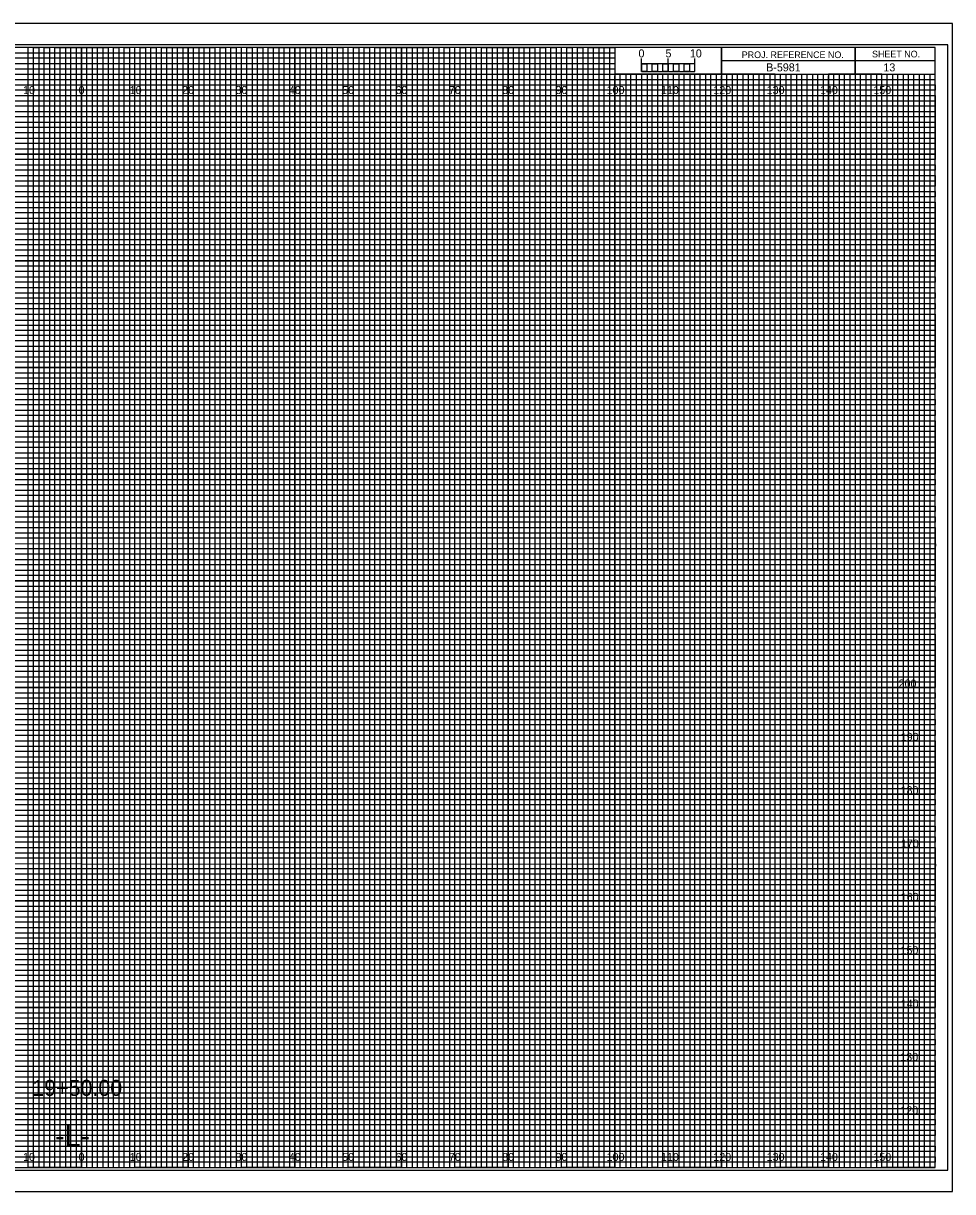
# Model space of a CAD drawing. Extents: x -13 to 323, y -5 to 4174.
# Drawn here: x 149.1 to 323.3, y 1535.5 to 1754.5 of the extents above; entities that cross this region are included whole.
import ezdxf

# ---------------------------------------------------------------- set-up
doc = ezdxf.new("R2010")
doc.units = 0
for name, color, linetype in [('Exist Cross Section Cell', 7, 'Continuous'), ('Exist XS Center Line Elevation Label', 7, 'Continuous'), ('Exist XS Ground Line', 7, 'Continuous'), ('Prop CMT Concrete Structures', 7, 'Continuous'), ('Prop CMT Guardrail Graphics', 7, 'Continuous'), ('Prop CMT Pvmt Course 1', 7, 'Continuous'), ('Prop CMT Pvmt Course 2', 7, 'Continuous'), ('Prop CMT Pvmt Course 3', 7, 'Continuous'), ('Prop CMT Pvmt Surface', 7, 'Continuous'), ('Prop CMT Shld Paved Course 1', 7, 'Continuous'), ('Prop CMT Shld Paved Course 2', 7, 'Continuous'), ('Prop CMT Shld Paved Course 3', 7, 'Continuous'), ('Prop CMT Subgrade Earthwork', 7, 'Continuous'), ('Prop XS Ditch Standard Text', 7, 'Continuous'), ('Prop XS SE Text', 7, 'Continuous'), ('Prop XS Side Slope Text', 7, 'Continuous'), ('Scratch_Level_0', 7, 'Continuous')]:
    doc.layers.add(name, color=color, linetype=linetype)

msp = doc.modelspace()

# ---------------------------------------------------------------- linework, layer by layer
at = {"layer": 'Exist XS Center Line Elevation Label'}
for points in [[(145, 1540), (155, 1540), (155, 1750), (165, 1750), (165, 1540), (175, 1540), (175, 1750), (185, 1750), (185, 1540), (195, 1540), (195, 1750), (205, 1750), (205, 1540), (215, 1540), (215, 1750), (225, 1750), (225, 1540), (235, 1540), (235, 1750), (245, 1750), (245, 1540), (255, 1540), (255, 1750), (259.93, 1750), (260, 1750), (260, 1745), (264.99, 1745), (264.99, 1540), (275, 1540), (275, 1745), (285, 1745), (285, 1540), (295, 1540), (295, 1745), (305, 1745), (305, 1540), (315, 1540), (315, 1745)], [(0, 1745), (275, 1745)], [(0, 1725), (320, 1725), (320, 1735), (0, 1735)], [(0, 1705), (320, 1705), (320, 1715), (0, 1715)], [(0, 1685), (320, 1685), (320, 1695), (0, 1695)], [(0, 1665), (320, 1665), (320, 1675), (0, 1675)], [(0, 1645), (320, 1645), (320, 1655), (0, 1655)], [(0, 1625), (320, 1625), (320, 1635), (0, 1635)], [(0, 1605), (320, 1605), (320, 1615), (0, 1615)], [(0, 1585), (320, 1585), (320, 1595), (0, 1595)], [(0, 1565), (320, 1565), (320, 1575), (0, 1575)], [(0, 1545), (320, 1545), (320, 1555), (0, 1555)]]:
    msp.add_lwpolyline(points, dxfattribs=at)
at = {"layer": 'Exist XS Ground Line'}
for p, q in [((150, 1750), (140, 1750)), ((150, 1540), (150, 1750)), ((170, 1750), (160, 1750)), ((160, 1750), (160, 1540)), ((170, 1540), (170, 1750)), ((190, 1750), (180, 1750)), ((180, 1750), (180, 1540)), ((190, 1540), (190, 1750)), ((210, 1750), (200, 1750)), ((200, 1750), (200, 1540)), ((210, 1540), (210, 1750)), ((230, 1750), (220, 1750)), ((220, 1750), (220, 1540)), ((230, 1540), (230, 1750)), ((250, 1750), (240, 1750)), ((240, 1750), (240, 1540)), ((250, 1540), (250, 1750)), ((260, 1750), (260, 1540)), ((270, 1540), (270, 1745)), ((290, 1745), (280, 1745)), ((280, 1745), (280, 1540)), ((290, 1540), (290, 1745)), ((310, 1745), (300, 1745)), ((300, 1745), (300, 1540)), ((310, 1540), (310, 1745)), ((160, 1540), (150, 1540)), ((180, 1540), (170, 1540)), ((200, 1540), (190, 1540)), ((220, 1540), (210, 1540)), ((240, 1540), (230, 1540)), ((260, 1540), (250, 1540)), ((280, 1540), (270, 1540)), ((300, 1540), (290, 1540)), ((320, 1540), (310, 1540)), ((320, 1540), (320, 1540))]:
    msp.add_line(p, q, dxfattribs=at)
for points in [[(0, 1740), (320, 1740), (320, 1730), (0, 1730)], [(0, 1720), (320, 1720), (320, 1710), (0, 1710)], [(0, 1700), (320, 1700), (320, 1690), (0, 1690)], [(0, 1680), (320, 1680), (320, 1670), (0, 1670)], [(0, 1660), (320, 1660), (320, 1650), (0, 1650)], [(0, 1640), (320, 1640), (320, 1630), (0, 1630)], [(0, 1620), (320, 1620), (320, 1610), (0, 1610)], [(0, 1600), (320, 1600), (320, 1590), (0, 1590)], [(0, 1580), (320, 1580), (320, 1570), (0, 1570)], [(0, 1560), (320, 1560), (320, 1550), (0, 1550)]]:
    msp.add_lwpolyline(points, dxfattribs=at)
at = {"layer": 'Prop CMT Pvmt Course 1'}
for p, q in [((323.3, 1754.5), (-13.4, 1754.5)), ((-13.4, 1535.5), (323.3, 1535.5))]:
    msp.add_line(p, q, dxfattribs=at)
at = {"layer": 'Prop CMT Pvmt Course 2'}
msp.add_lwpolyline([(-13.4, 1535.5), (323.3, 1535.5), (323.3, 1754.5), (-13.4, 1754.5)], close=True, dxfattribs=at)
at = {"layer": 'Prop CMT Pvmt Course 3'}
msp.add_lwpolyline([(-10.8, 1539.5), (322.4, 1539.5), (322.4, 1750.5), (-10.8, 1750.5)], close=True, dxfattribs=at)
at = {"layer": 'Prop CMT Shld Paved Course 1'}
for p, q in [((305, 1750), (305, 1745)), ((305, 1745), (305, 1750)), ((280, 1747.5), (280, 1745)), ((320, 1747.49), (280, 1747.49)), ((280, 1745), (320, 1745))]:
    msp.add_line(p, q, dxfattribs=at)
for points in [[(320, 1750), (0, 1750), (0, 1540), (320, 1540)], [(280, 1750), (260, 1750), (260, 1745.03), (280, 1745.03)], [(320, 1750), (280, 1750), (280, 1745), (320, 1745)]]:
    msp.add_lwpolyline(points, close=True, dxfattribs=at)
at = {"layer": 'Prop CMT Shld Paved Course 2'}
for p, q in [((267, 1745), (266.01, 1745)), ((266.01, 1745), (266.01, 1540)), ((267, 1540), (267, 1745)), ((269, 1745), (268, 1745)), ((268, 1745), (268, 1540)), ((269, 1540), (269, 1745)), ((266.01, 1540), (265, 1540)), ((268, 1540), (267, 1540))]:
    msp.add_line(p, q, dxfattribs=at)
for points in [[(150, 1540), (151, 1540), (151, 1750), (152, 1750), (152, 1540)], [(152, 1540), (153, 1540), (153, 1750), (154, 1750), (154, 1540)], [(155, 1540), (156, 1540), (156, 1750), (157, 1750), (157, 1540)], [(157, 1540), (158, 1540), (158, 1750), (159, 1750), (159, 1540)], [(160, 1540), (161, 1540), (161, 1750), (162, 1750), (162, 1540)], [(162, 1540), (163, 1540), (163, 1750), (164, 1750), (164, 1540)], [(165, 1540), (166, 1540), (166, 1750), (167, 1750), (167, 1540)], [(167, 1540), (168, 1540), (168, 1750), (169, 1750), (169, 1540)], [(170, 1540), (171, 1540), (171, 1750), (172, 1750), (172, 1540)], [(172, 1540), (173, 1540), (173, 1750), (174, 1750), (174, 1540)], [(175, 1540), (176, 1540), (176, 1750), (177, 1750), (177, 1540)], [(177, 1540), (178, 1540), (178, 1750), (179, 1750), (179, 1540)], [(180, 1540), (181, 1540), (181, 1750), (182, 1750), (182, 1540)], [(182, 1540), (183, 1540), (183, 1750), (184, 1750), (184, 1540)], [(185, 1540), (186, 1540), (186, 1750), (187, 1750), (187, 1540)], [(187, 1540), (188, 1540), (188, 1750), (189, 1750), (189, 1540)], [(190, 1540), (191, 1540), (191, 1750), (192, 1750), (192, 1540)], [(192, 1540), (193, 1540), (193, 1750), (194, 1750), (194, 1540)], [(195, 1540), (196, 1540), (196, 1750), (197, 1750), (197, 1540)], [(197, 1540), (198, 1540), (198, 1750), (199, 1750), (199, 1540)], [(200, 1540), (201, 1540), (201, 1750), (202, 1750), (202, 1540)], [(202, 1540), (203, 1540), (203, 1750), (204, 1750), (204, 1540)], [(205, 1540), (206, 1540), (206, 1750), (207, 1750), (207, 1540)], [(207, 1540), (208, 1540), (208, 1750), (209, 1750), (209, 1540)], [(210, 1540), (211, 1540), (211, 1750), (212, 1750), (212, 1540)], [(212, 1540), (213, 1540), (213, 1750), (214, 1750), (214, 1540)], [(215, 1540), (216, 1540), (216, 1750), (217, 1750), (217, 1540)], [(217, 1540), (218, 1540), (218, 1750), (219, 1750), (219, 1540)], [(220, 1540), (221, 1540), (221, 1750), (222, 1750), (222, 1540)], [(222, 1540), (223, 1540), (223, 1750), (224, 1750), (224, 1540)], [(225, 1540), (226, 1540), (226, 1750), (227, 1750), (227, 1540)], [(227, 1540), (228, 1540), (228, 1750), (229, 1750), (229, 1540)], [(230, 1540), (231, 1540), (231, 1750), (232, 1750), (232, 1540)], [(232, 1540), (233, 1540), (233, 1750), (234, 1750), (234, 1540)], [(235, 1540), (236, 1540), (236, 1750), (237, 1750), (237, 1540)], [(237, 1540), (238, 1540), (238, 1750), (239, 1750), (239, 1540)], [(240, 1540), (241, 1540), (241, 1750), (242, 1750), (242, 1540)], [(242, 1540), (243, 1540), (243, 1750), (244, 1750), (244, 1540)], [(245, 1540), (246, 1540), (246, 1750), (247, 1750), (247, 1540)], [(247, 1540), (248, 1540), (248, 1750), (249, 1750), (249, 1540)], [(250, 1540), (251, 1540), (251, 1750), (252, 1750), (252, 1540)], [(252, 1540), (253, 1540), (253, 1750), (254, 1750), (254, 1540)], [(255, 1540), (256, 1540), (256, 1750), (257, 1750), (257, 1540)], [(257, 1540), (258, 1540), (258, 1750), (259, 1750), (259, 1540)], [(260, 1540), (261, 1540), (261, 1745), (262.02, 1745), (262.02, 1540)], [(262, 1540), (263, 1540), (263, 1745), (263.99, 1745), (263.99, 1540)], [(270, 1540), (270.98, 1540), (270.98, 1745), (272, 1745), (272, 1540)], [(272, 1540), (273, 1540), (273, 1745), (274.05, 1745), (274.05, 1540)], [(275, 1540), (276, 1540), (276, 1745), (277, 1745), (277, 1540)], [(277, 1540), (278, 1540), (278, 1745), (279, 1745), (279, 1540)], [(280, 1540), (281, 1540), (281, 1745), (282, 1745), (282, 1540)], [(282, 1540), (283, 1540), (283, 1745), (284, 1745), (284, 1540)], [(285, 1540), (286, 1540), (286, 1745), (287, 1745), (287, 1540)], [(287, 1540), (288, 1540), (288, 1745), (289, 1745), (289, 1540)], [(290, 1540), (291, 1540), (291, 1745), (292, 1745), (292, 1540)], [(292, 1540), (293, 1540), (293, 1745), (294, 1745), (294, 1540)], [(295, 1540), (296, 1540), (296, 1745), (297, 1745), (297, 1540)], [(297, 1540), (298, 1540), (298, 1745), (299, 1745), (299, 1540)], [(300, 1540), (301, 1540), (301, 1745), (302, 1745), (302, 1540)], [(302, 1540), (303, 1540), (303, 1745), (304, 1745), (304, 1540)], [(305, 1540), (306, 1540), (306, 1745), (307, 1745), (307, 1540)], [(307, 1540), (308, 1540), (308, 1745), (309, 1745), (309, 1540)], [(310, 1540), (311, 1540), (311, 1745), (312, 1745), (312, 1540)], [(312, 1540), (313, 1540), (313, 1745), (314, 1745), (314, 1540)], [(315, 1540), (316, 1540), (316, 1745), (317, 1745), (317, 1540)], [(317, 1540), (318, 1540), (318, 1745), (319, 1745), (319, 1540)]]:
    msp.add_lwpolyline(points, dxfattribs=at)
at = {"layer": 'Prop CMT Shld Paved Course 3'}
for p, q in [((265, 1745.49), (265, 1747.9)), ((265, 1746.9), (265, 1747.9)), ((270, 1745.49), (270, 1747.9)), ((275, 1745.49), (275, 1747.9)), ((275, 1746.9), (275, 1747.9))]:
    msp.add_line(p, q, dxfattribs=at)
for points in [[(275, 1746.9), (265, 1746.9), (265, 1745.49), (275, 1745.49)], [(265, 1746.9), (266, 1746.9), (266, 1745.49), (265, 1745.49)], [(267, 1746.9), (268, 1746.9), (268, 1745.49), (267, 1745.49)], [(269, 1746.9), (270, 1746.9), (270, 1745.49), (269, 1745.49)], [(271, 1746.9), (272, 1746.9), (272, 1745.49), (271, 1745.49)], [(273, 1746.9), (274, 1746.9), (274, 1745.49), (273, 1745.49)]]:
    msp.add_lwpolyline(points, close=True, dxfattribs=at)
at = {"layer": 'Prop CMT Subgrade Earthwork'}
for p, q in [((150, 1540), (150, 1750)), ((160, 1540), (160, 1750)), ((170, 1540), (170, 1750)), ((180, 1540), (180, 1750)), ((190, 1540), (190, 1750)), ((200, 1540), (200, 1750)), ((210, 1540), (210, 1750)), ((220, 1540), (220, 1750)), ((230, 1540), (230, 1750)), ((240, 1540), (240, 1750)), ((250, 1540), (250, 1750)), ((260, 1540), (260, 1744.69)), ((270, 1540), (270, 1744.69)), ((280, 1540), (280, 1744.69)), ((290, 1540), (290, 1744.69)), ((300, 1540), (300, 1744.69)), ((310, 1540), (310, 1744.69)), ((0, 1740), (320, 1740)), ((0, 1730), (320, 1730)), ((0, 1720), (320, 1720)), ((0, 1710), (320, 1710)), ((0, 1700), (320, 1700)), ((0, 1690), (320, 1690)), ((0, 1680), (320, 1680)), ((0, 1670), (320, 1670)), ((0, 1660), (320, 1660)), ((0, 1650), (320, 1650)), ((0, 1640), (320, 1640)), ((0, 1630), (320, 1630)), ((0, 1620), (320, 1620)), ((0, 1610), (320, 1610)), ((0, 1600), (320, 1600)), ((0, 1590), (320, 1590)), ((0, 1580), (320, 1580)), ((0, 1570), (320, 1570)), ((0, 1560), (320, 1560)), ((0, 1550), (320, 1550))]:
    msp.add_line(p, q, dxfattribs=at)
at = {"layer": 'Scratch_Level_0'}
for p, q in [((0, 1749), (260, 1749)), ((260, 1747.98), (0, 1747.98)), ((260, 1749), (260, 1747.98)), ((0, 1747), (260, 1747)), ((260, 1745.89), (0, 1745.89)), ((260, 1747), (260, 1745.89)), ((0, 1744), (320, 1744))]:
    msp.add_line(p, q, dxfattribs=at)
for points in [[(0, 1743), (270, 1743), (320, 1743), (320, 1742), (0, 1742)], [(0, 1741), (320, 1741), (320, 1739), (0, 1739)], [(0, 1738), (320, 1738), (320, 1737), (0, 1736.98)], [(0, 1736), (320, 1736), (320, 1734), (0, 1734)], [(0, 1733), (320, 1733), (320, 1732), (0, 1732)], [(0, 1731), (320, 1731), (320, 1729), (0, 1729)], [(0, 1728), (320, 1728), (320, 1727), (0, 1727)], [(0, 1726), (320, 1726), (320, 1724), (0, 1724)], [(0, 1723), (320, 1723), (320, 1722), (0, 1722)], [(0, 1721), (320, 1721), (320, 1719), (0, 1719)], [(0, 1718), (320, 1718), (320, 1717), (0, 1717)], [(0, 1716), (320, 1716), (320, 1713.95), (320, 1713), (320, 1712), (0, 1712)], [(0, 1714), (320, 1714), (320, 1713), (0, 1713)], [(0, 1711), (320, 1711), (320, 1709), (0, 1709.03)], [(0, 1709.03), (320, 1709), (320, 1708), (0, 1708)], [(0, 1707), (320, 1707), (320, 1706), (0, 1706)], [(0, 1704), (320, 1704), (320, 1703), (0, 1703)], [(0, 1702), (320, 1702), (320, 1701), (0, 1701)], [(-0.07, 1698.89), (320, 1698.89), (320, 1697.88), (-0.07, 1697.88)], [(0, 1697), (320, 1697), (320, 1696), (0, 1696)], [(0, 1694), (320, 1694), (320, 1693), (0, 1693)], [(0, 1692), (320, 1692), (320, 1691), (0, 1691)], [(0, 1689), (320, 1689), (320, 1688), (0, 1688)], [(0, 1687), (320, 1687), (320, 1686), (0, 1686)], [(0, 1684), (320, 1684), (320, 1683), (0, 1683)], [(0, 1682), (320, 1682), (320, 1681), (0, 1681)], [(0, 1679), (320, 1679), (319.99, 1677.98), (0, 1678)], [(0, 1677), (320, 1677), (320, 1676), (0, 1676)], [(0, 1674), (320, 1674), (320, 1673), (0, 1673)], [(0, 1672), (320, 1672), (320, 1671), (0, 1671)], [(0, 1669), (320, 1669), (320, 1668), (0, 1668)], [(0, 1667), (320, 1667), (320, 1666), (0, 1666)], [(0, 1664), (320, 1664), (320, 1663), (0, 1663)], [(0, 1662), (320, 1662), (320, 1661), (0, 1661)], [(0, 1659), (320, 1659), (320, 1658), (0, 1658)], [(0, 1656.99), (320.07, 1656.91), (320, 1656), (0, 1656)], [(0, 1654), (320, 1654), (320, 1653), (0, 1653)], [(0, 1652), (320, 1652), (320, 1651), (0, 1651)], [(0, 1649), (320, 1649), (320, 1648), (0, 1648)], [(0, 1647), (320, 1647), (320, 1646), (0, 1646)], [(0, 1644), (320, 1644), (320, 1643), (0, 1643)], [(0, 1642), (320, 1642), (320, 1641), (0, 1641)], [(0, 1639), (320, 1639), (320, 1638), (0, 1638)], [(0, 1637), (320, 1637), (320, 1636), (0, 1636)], [(0, 1634), (320, 1634), (320, 1633), (0, 1633)], [(0, 1632), (320, 1632), (320, 1631), (0, 1631)], [(0, 1629), (320, 1629), (320, 1628), (0, 1628)], [(0, 1627), (320, 1627), (320, 1626), (0, 1626)], [(0, 1624), (320, 1624), (320, 1623), (0, 1623)], [(0, 1622), (320, 1622), (320, 1621), (0, 1621)], [(0, 1619), (320, 1619), (319.99, 1617.98), (0, 1618)], [(0, 1617), (320, 1617), (320, 1616), (0, 1616)], [(0, 1614), (320, 1614), (320, 1613), (0, 1613)], [(0, 1612), (320, 1612), (320, 1611), (0, 1611)], [(0, 1609), (320, 1609), (320, 1608), (0, 1608)], [(0, 1607), (320, 1607), (320, 1606), (0, 1606)], [(0, 1604), (320, 1604), (320, 1603), (0, 1603)], [(0, 1602), (320, 1602), (320, 1601), (0, 1601)], [(0, 1599), (320, 1599), (320, 1598), (0, 1598)], [(0, 1596.99), (320.07, 1596.91), (320, 1596), (0, 1596)], [(0, 1594), (320, 1594), (320, 1593), (0, 1593)], [(0, 1592), (320, 1592), (320, 1591), (0, 1591)], [(0, 1589), (320, 1589), (320, 1588), (0, 1588)], [(0, 1587), (320, 1587), (320, 1586), (0, 1586)], [(0, 1584), (320, 1584), (320, 1583), (0, 1583)], [(0, 1582), (320, 1582), (320, 1581), (0, 1581)], [(0, 1579), (320, 1579), (320, 1578), (0, 1578)], [(0, 1577), (320, 1577), (320, 1576), (0, 1576)], [(0, 1574), (320, 1574), (320, 1573), (0, 1573)], [(0, 1572), (320, 1572), (320, 1571), (0, 1571)], [(0, 1569), (320, 1569), (320, 1568), (0, 1568)], [(0, 1567), (320, 1567), (320, 1566), (0, 1566)], [(0, 1564), (320, 1564), (320, 1563), (0, 1563)], [(0, 1562), (320, 1562), (320, 1561), (0, 1561)], [(0, 1559), (320, 1559), (320, 1558), (0, 1558)], [(0, 1557), (320, 1557), (320, 1556), (0, 1556)], [(0, 1554), (320, 1554), (320, 1553), (0, 1553)], [(0, 1552), (320, 1552), (320, 1551), (0, 1551)], [(0, 1549), (320, 1549), (320, 1548), (0, 1548)], [(0, 1547), (320, 1547), (320, 1546), (0, 1546)], [(0, 1544), (320, 1544), (320, 1543), (0, 1543)], [(0, 1542), (320, 1542), (320, 1541), (0, 1541)]]:
    msp.add_lwpolyline(points, dxfattribs=at)

# ---------------------------------------------------------------- texts
at = {"layer": 'Exist Cross Section Cell'}
for s, p in [('10', (149.04, 1741.25)), ('0', (159.45, 1741.25)), ('0', (159.45, 1741.25)), ('10', (169.04, 1741.25)), ('20', (178.86, 1741.25)), ('30', (188.86, 1741.25)), ('40', (198.86, 1741.25)), ('50', (208.86, 1741.25)), ('60', (218.86, 1741.25)), ('70', (228.86, 1741.25)), ('80', (238.86, 1741.25)), ('90', (248.86, 1741.25)), ('100', (258.44, 1741.25)), ('110', (268.62, 1741.25)), ('120', (278.44, 1741.25)), ('130', (288.44, 1741.25)), ('140', (298.44, 1741.25)), ('150', (308.44, 1741.25)), ('10', (149.04, 1541.25)), ('0', (159.45, 1541.25)), ('0', (159.45, 1541.25)), ('10', (169.04, 1541.25)), ('20', (178.86, 1541.25)), ('30', (188.86, 1541.25)), ('40', (198.86, 1541.25)), ('50', (208.86, 1541.25)), ('60', (218.86, 1541.25)), ('70', (228.86, 1541.25)), ('80', (238.86, 1541.25)), ('90', (248.86, 1541.25)), ('100', (258.44, 1541.25)), ('110', (268.62, 1541.25)), ('120', (278.44, 1541.25)), ('130', (288.44, 1541.25)), ('140', (298.44, 1541.25)), ('150', (308.44, 1541.25))]:
    msp.add_text(s, height=1.5, dxfattribs=at).set_placement(p)
at = {"layer": 'Prop CMT Concrete Structures'}
msp.add_text('19+50.00', height=3, dxfattribs=at).set_placement((150.77, 1553.45))
at = {"layer": 'Prop CMT Guardrail Graphics'}
for s, p in [('200', (313.17, 1630)), ('190', (313.57, 1620)), ('180', (313.55, 1610)), ('170', (313.61, 1600)), ('160', (313.57, 1590)), ('150', (313.52, 1580)), ('140', (313.57, 1570)), ('130', (313.49, 1560)), ('120', (313.5, 1550))]:
    msp.add_text(s, height=1.5, dxfattribs=at).set_placement(p)
at = {"layer": 'Prop CMT Pvmt Surface'}
for s, p in [('5', (269.47, 1748.12)), ('10', (274.04, 1748.12))]:
    msp.add_text(s, height=1.5, dxfattribs=at).set_placement(p)
at = {"layer": 'Prop CMT Shld Paved Course 1'}
for s, p in [('PROJ. REFERENCE NO.', (283.77, 1747.99)), ('SHEET NO.', (308.19, 1748.12))]:
    msp.add_text(s, height=1.25, dxfattribs=at).set_placement(p)
at = {"layer": 'Prop CMT Shld Paved Course 3'}
msp.add_text('0', height=1.5, dxfattribs=at).set_placement((264.41, 1748.12))
at = {"layer": 'Prop XS Ditch Standard Text'}
msp.add_text('-L-', height=4, dxfattribs=at).set_placement((155.06, 1544))
at = {"layer": 'Prop XS SE Text'}
msp.add_text(' B-5981', height=1.5, dxfattribs=at).set_placement((287.79, 1745.5))
at = {"layer": 'Prop XS Side Slope Text'}
msp.add_text('13', height=1.5, dxfattribs=at).set_placement((310.32, 1745.5))

doc.saveas('drawing.dxf')
